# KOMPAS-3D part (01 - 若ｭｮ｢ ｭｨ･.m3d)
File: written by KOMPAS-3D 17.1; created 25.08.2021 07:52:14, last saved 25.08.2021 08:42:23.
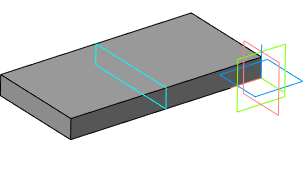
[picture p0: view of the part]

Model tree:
1. Эскиз:1
2. Элемент выдавливания:1
     Расстояние 2 = 100
3. Средняя плоскость:1
4. Отрезок:1
     Точка 1. Смещение (% от длины кривой) = 50; Точка 2. Смещение (% от длины кривой) = 50; Длина отрезка = 100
